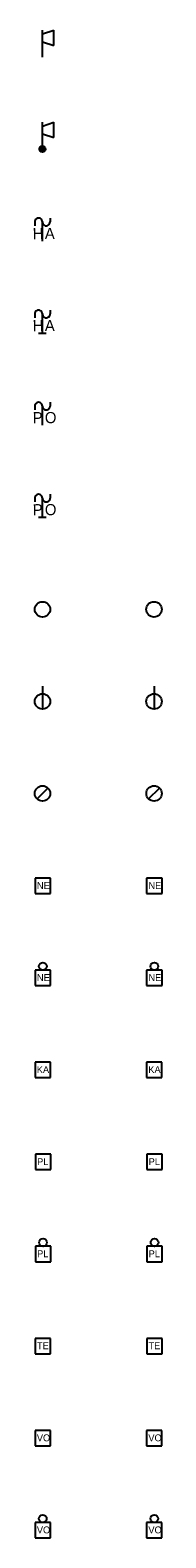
# Model space of a CAD drawing. Extents: x -808813 to -807709, y -1017258 to -1016779.
# Drawn here: x -808107.8 to -808099.4, y -1016985.7 to -1016887.5 of the extents above; entities that cross this region are included whole.
import ezdxf

# ---------------------------------------------------------------- set-up
doc = ezdxf.new("R2010")
doc.units = 0
doc.layers.add('PovrZnIS_body', color=7, linetype='Continuous')

msp = doc.modelspace()

# ---------------------------------------------------------------- linework, layer by layer
at = {"layer": 'PovrZnIS_body'}
for p, q in [((-808107.22, -1016889.27), (-808107.22, -1016887.52)), ((-808107.22, -1016887.77), (-808106.47, -1016887.52)), ((-808106.47, -1016888.52), (-808106.47, -1016887.52)), ((-808107.22, -1016888.27), (-808106.47, -1016888.52)), ((-808107.219, -1016895.262), (-808107.219, -1016893.512)), ((-808107.219, -1016893.762), (-808106.469, -1016893.512)), ((-808106.469, -1016894.512), (-808106.469, -1016893.512)), ((-808107.219, -1016894.262), (-808106.469, -1016894.512)), ((-808107.715, -1016900.002), (-808107.718, -1016900.254)), ((-808107.218, -1016901.254), (-808107.218, -1016900.004)), ((-808106.718, -1016899.754), (-808106.716, -1016900.002)), ((-808106.717, -1016905.746), (-808106.715, -1016905.994)), ((-808107.714, -1016905.994), (-808107.717, -1016906.246)), ((-808107.217, -1016907.246), (-808107.217, -1016905.996)), ((-808107.467, -1016907.246), (-808106.967, -1016907.246)), ((-808106.716, -1016911.738), (-808106.714, -1016911.986)), ((-808107.713, -1016911.986), (-808107.716, -1016912.238)), ((-808107.216, -1016913.238), (-808107.216, -1016911.988)), ((-808107.712, -1016917.978), (-808107.715, -1016918.23)), ((-808107.215, -1016919.23), (-808107.215, -1016917.98)), ((-808106.715, -1016917.73), (-808106.713, -1016917.978)), ((-808107.465, -1016919.23), (-808106.965, -1016919.23)), ((-808107.213, -1016930.214), (-808107.213, -1016931.714)), ((-808099.954, -1016930.214), (-808099.954, -1016931.714)), ((-808107.565, -1016937.559), (-808106.858, -1016936.852)), ((-808100.307, -1016937.559), (-808099.6, -1016936.852)), ((-808106.691, -1016942.716), (-808107.691, -1016942.716)), ((-808107.691, -1016942.716), (-808107.691, -1016943.716)), ((-808106.691, -1016943.716), (-808106.691, -1016942.716)), ((-808099.433, -1016942.716), (-808100.433, -1016942.716)), ((-808100.433, -1016942.716), (-808100.433, -1016943.716)), ((-808099.433, -1016943.716), (-808099.433, -1016942.716)), ((-808107.691, -1016943.716), (-808106.691, -1016943.716)), ((-808100.433, -1016943.716), (-808099.433, -1016943.716)), ((-808106.691, -1016948.708), (-808107.691, -1016948.708)), ((-808107.691, -1016948.708), (-808107.691, -1016949.708)), ((-808106.691, -1016949.708), (-808106.691, -1016948.708)), ((-808099.433, -1016948.708), (-808100.433, -1016948.708)), ((-808100.433, -1016948.708), (-808100.433, -1016949.708)), ((-808099.433, -1016949.708), (-808099.433, -1016948.708)), ((-808107.691, -1016949.708), (-808106.691, -1016949.708)), ((-808100.433, -1016949.708), (-808099.433, -1016949.708)), ((-808106.698, -1016954.7), (-808107.698, -1016954.7)), ((-808107.698, -1016954.7), (-808107.698, -1016955.7)), ((-808106.698, -1016955.7), (-808106.698, -1016954.7)), ((-808099.439, -1016954.7), (-808100.439, -1016954.7)), ((-808100.439, -1016954.7), (-808100.439, -1016955.7)), ((-808099.439, -1016955.7), (-808099.439, -1016954.7)), ((-808107.698, -1016955.7), (-808106.698, -1016955.7)), ((-808100.439, -1016955.7), (-808099.439, -1016955.7)), ((-808106.679, -1016960.692), (-808107.679, -1016960.692)), ((-808107.679, -1016960.692), (-808107.679, -1016961.692)), ((-808106.679, -1016961.692), (-808106.679, -1016960.692)), ((-808099.42, -1016960.692), (-808100.42, -1016960.692)), ((-808100.42, -1016960.692), (-808100.42, -1016961.692)), ((-808099.42, -1016961.692), (-808099.42, -1016960.692)), ((-808107.679, -1016961.692), (-808106.679, -1016961.692)), ((-808100.42, -1016961.692), (-808099.42, -1016961.692)), ((-808106.678, -1016966.684), (-808107.678, -1016966.684)), ((-808107.678, -1016966.684), (-808107.678, -1016967.684)), ((-808106.678, -1016967.684), (-808106.678, -1016966.684)), ((-808099.419, -1016966.684), (-808100.419, -1016966.684)), ((-808100.419, -1016966.684), (-808100.419, -1016967.684)), ((-808099.419, -1016967.684), (-808099.419, -1016966.684)), ((-808107.678, -1016967.684), (-808106.678, -1016967.684)), ((-808100.419, -1016967.684), (-808099.419, -1016967.684)), ((-808106.687, -1016972.677), (-808107.687, -1016972.677)), ((-808107.687, -1016972.677), (-808107.687, -1016973.677)), ((-808106.687, -1016973.677), (-808106.687, -1016972.677)), ((-808099.429, -1016972.677), (-808100.429, -1016972.677)), ((-808100.429, -1016972.677), (-808100.429, -1016973.677)), ((-808099.429, -1016973.677), (-808099.429, -1016972.677)), ((-808107.687, -1016973.677), (-808106.687, -1016973.677)), ((-808100.429, -1016973.677), (-808099.429, -1016973.677)), ((-808106.696, -1016978.668), (-808107.696, -1016978.668)), ((-808107.696, -1016978.668), (-808107.696, -1016979.668)), ((-808106.696, -1016979.668), (-808106.696, -1016978.668)), ((-808099.437, -1016978.668), (-808100.437, -1016978.668)), ((-808100.437, -1016978.668), (-808100.437, -1016979.668)), ((-808099.437, -1016979.668), (-808099.437, -1016978.668)), ((-808107.696, -1016979.668), (-808106.696, -1016979.668)), ((-808100.437, -1016979.668), (-808099.437, -1016979.668)), ((-808106.695, -1016984.66), (-808107.695, -1016984.66)), ((-808107.695, -1016984.66), (-808107.695, -1016985.66)), ((-808106.695, -1016985.66), (-808106.695, -1016984.66)), ((-808099.436, -1016984.66), (-808100.436, -1016984.66)), ((-808100.436, -1016984.66), (-808100.436, -1016985.66)), ((-808099.436, -1016985.66), (-808099.436, -1016984.66)), ((-808107.695, -1016985.66), (-808106.695, -1016985.66)), ((-808100.436, -1016985.66), (-808099.436, -1016985.66))]:
    msp.add_line(p, q, dxfattribs=at)
for centre in [(-808107.214, -1016925.222), (-808099.955, -1016925.222), (-808107.213, -1016931.214), (-808099.954, -1016931.214), (-808107.212, -1016937.206), (-808099.953, -1016937.206)]:
    msp.add_circle(centre, 0.5, dxfattribs=at)
for centre, radius, start, end in [((-808107.468, -1016900.002), 0.248, 359.99988, 180.00011), ((-808106.968, -1016900.003), 0.252, 179.8862, 0.11379)]:
    msp.add_arc(centre, radius, start, end, dxfattribs=at)
for centre, major_axis, ratio in [((-808107.219, -1016895.262), (0.141, -0.141), 0.999999), ((-808107.219, -1016895.262), (0.0884, -0.0884), 0.999999), ((-808107.219, -1016895.262), (0.0354, -0.0354), 0.999999), ((-808107.191, -1016948.458), (0.177, -0.177), 0.999996), ((-808099.933, -1016948.458), (0.177, -0.177), 0.999996), ((-808107.178, -1016966.434), (0.177, -0.177), 0.999996), ((-808099.92, -1016966.434), (0.177, -0.177), 0.999996), ((-808107.195, -1016984.409), (0.177, -0.177), 0.999996), ((-808099.937, -1016984.409), (0.177, -0.177), 0.999996)]:
    msp.add_ellipse(centre, major_axis=major_axis, ratio=ratio, dxfattribs=at)
for centre, major_axis, ratio, start_param, end_param in [((-808107.466, -1016905.994), (-0.175, 0.175), 0.999997, 3.926989, 7.068585), ((-808106.967, -1016905.994), (-0.178, 0.178), 0.999997, 0.783412, 3.928977), ((-808107.466, -1016911.986), (-0.175, 0.175), 0.999999, 3.926989, 7.068585), ((-808106.966, -1016911.987), (-0.178, 0.178), 0.999999, 0.783412, 3.928977), ((-808107.464, -1016917.978), (-0.175, -0.175), 0.999997, 2.356192, 5.497789), ((-808106.965, -1016917.978), (-0.178, -0.178), 0.999997, 5.495801, 8.641366)]:
    msp.add_ellipse(centre, major_axis=major_axis, ratio=ratio, start_param=start_param, end_param=end_param, dxfattribs=at)

# ---------------------------------------------------------------- texts
for s, height, rotation, p in [('H', 0.725, 1.37388, (-808107.843, -1016901.129)), ('H', 0.725, 1.37379, (-808107.842, -1016907.121)), ('A', 0.725, 359.99992, (-808107.061, -1016907.11)), ('P', 0.725, 1.37384, (-808107.841, -1016913.113)), ('O', 0.725, 359.99996, (-808107.059, -1016913.102)), ('P', 0.725, 1.37395, (-808107.841, -1016919.105)), ('O', 0.725, 0.00007, (-808107.059, -1016919.093)), ('NE', 0.45, 359.99996, (-808107.576, -1016943.423)), ('NE', 0.45, 359.99996, (-808100.318, -1016943.423)), ('NE', 0.45, 359.99988, (-808107.575, -1016949.415)), ('NE', 0.45, 359.99988, (-808100.317, -1016949.415)), ('KA', 0.45, 359.99996, (-808107.584, -1016955.407)), ('KA', 0.45, 359.99996, (-808100.325, -1016955.407)), ('PL', 0.45, 359.99996, (-808107.564, -1016961.399)), ('PL', 0.45, 359.99996, (-808100.306, -1016961.399)), ('PL', 0.45, 359.99988, (-808107.563, -1016967.391)), ('PL', 0.45, 359.99988, (-808100.305, -1016967.391)), ('TE', 0.45, 359.99996, (-808107.571, -1016973.383)), ('TE', 0.45, 359.99996, (-808100.313, -1016973.383)), ('VO', 0.45, 359.99996, (-808107.581, -1016979.375)), ('VO', 0.45, 359.99996, (-808100.322, -1016979.375)), ('VO', 0.45, 359.99988, (-808107.58, -1016985.367)), ('VO', 0.45, 359.99988, (-808100.321, -1016985.367))]:
    msp.add_text(s, height=height, rotation=rotation, dxfattribs=at).set_placement(p)
msp.add_text('A', height=0.725, dxfattribs=at).set_placement((-808107.061, -1016901.117))

doc.saveas('drawing.dxf')
